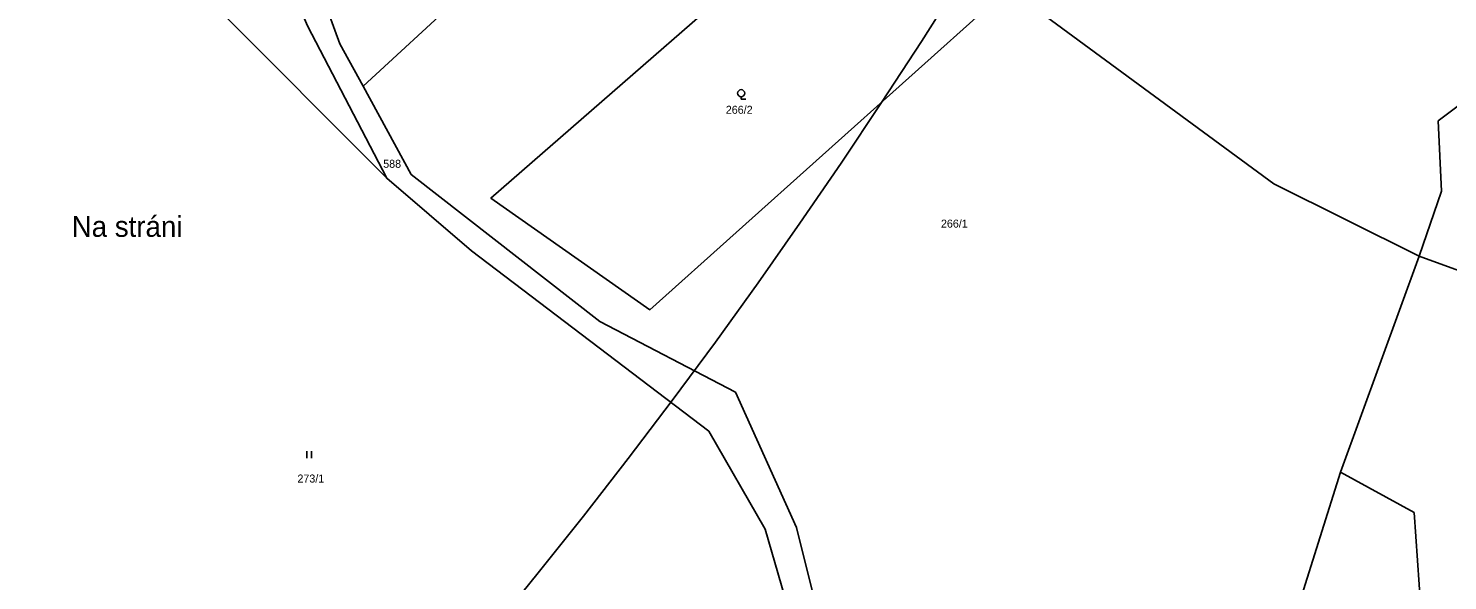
# Model space of a CAD drawing. Extents: x -680203 to -673936, y -1102717 to -1093650.
# Drawn here: x -675523.1 to -675221.6, y -1100209.9 to -1100092.5 of the extents above; entities that cross this region are included whole.
import ezdxf

# ---------------------------------------------------------------- set-up
doc = ezdxf.new("R2010")
doc.units = 0
for name, color, linetype in [('_Ideová část', 7, 'Continuous'), ('SOxx02xx_Staničení_Popis10', 7, 'Continuous'), ('SOxxxxxx_Koleje_hlavní_body_Popis10', 7, 'Continuous'), ('SOxxxxxx_Osa_bod_P', 7, 'Continuous'), ('x_prac', 7, 'Continuous')]:
    doc.layers.add(name, color=color, linetype=linetype)

msp = doc.modelspace()

# ---------------------------------------------------------------- linework, layer by layer
at = {"layer": '_Ideová část'}
msp.add_circle((-676417.7, -1099401.52), 1287.12, dxfattribs=at)
at = {"layer": 'SOxxxxxx_Koleje_hlavní_body_Popis10'}
for p, q in [((-675371.64, -1100107.03), (-675371.64, -1100107.53)), ((-675371.64, -1100107.53), (-675370.64, -1100107.53)), ((-675463.89, -1100183.86), (-675463.89, -1100182.36)), ((-675462.89, -1100183.86), (-675462.89, -1100182.36))]:
    msp.add_line(p, q, dxfattribs=at)
msp.add_circle((-675371.64, -1100106.28), 0.75, dxfattribs=at)
at = {"layer": 'x_prac'}
for p, q in [((-675414.33, -1100070.11), (-675451.95, -1100104.77)), ((-675244.33, -1100186.85), (-675227.61, -1100140.95))]:
    msp.add_line(p, q, dxfattribs=at)
for points in [[(-675488.6, -1099986.94), (-675490.8, -1100001.83), (-675490.85, -1100016.83), (-675483.97, -1100036.22), (-675479.36, -1100047.75), (-675463.07, -1100078.83), (-675456.93, -1100095.79), (-675451.95, -1100104.77)], [(-675504.01, -1100008.13), (-675497.05, -1100017.87), (-675485.06, -1100046.49), (-675472.26, -1100072.14), (-675463.76, -1100091.96), (-675446.93, -1100124.36)], [(-675227.61, -1100140.95), (-675258.46, -1100125.54), (-675331.04, -1100072.09), (-675370.73, -1100040.57), (-675378.15, -1100035.65)], [(-675446.93, -1100124.36), (-675483.47, -1100087.73), (-675482.46, -1100073.03), (-675526.45, -1100042.02), (-675541.96, -1100056.8)], [(-675317.7, -1100086.57), (-675391.04, -1100152.33), (-675424.81, -1100128.59), (-675349.68, -1100063.08), (-675317.7, -1100086.57)], [(-675227.61, -1100140.95), (-675222.85, -1100127.09), (-675223.59, -1100112.18), (-675207.93, -1100100.43)], [(-675451.95, -1100104.77), (-675441.73, -1100123.56), (-675401.64, -1100154.85), (-675372.85, -1100169.87), (-675359.9, -1100198.59), (-675347.26, -1100249.26), (-675337.16, -1100259.86), (-675318.61, -1100283.44)], [(-675344.14, -1100258.95), (-675351.41, -1100251.25), (-675366.51, -1100198.94), (-675378.54, -1100178.11), (-675428.96, -1100139.82), (-675446.93, -1100124.36)], [(-675227.61, -1100140.95), (-675204.48, -1100149.34), (-675198.43, -1100161.15), (-675198.38, -1100171.91)], [(-675244.33, -1100186.85), (-675252.98, -1100214.36), (-675263.97, -1100229.42), (-675265.63, -1100248.34), (-675275.06, -1100268.25), (-675279.29, -1100273.53)], [(-675246.15, -1100269.9), (-675236.86, -1100232.59), (-675226.94, -1100220.92), (-675228.67, -1100195.42), (-675244.33, -1100186.85)]]:
    msp.add_lwpolyline(points, dxfattribs=at)

# ---------------------------------------------------------------- texts
at = {"layer": 'SOxx02xx_Staničení_Popis10'}
msp.add_text('Na stráni', height=4.4, dxfattribs=at).set_placement((-675513.86, -1100136.82))
at = {"layer": 'SOxxxxxx_Osa_bod_P'}
for s, p in [('266/2', (-675374.9, -1100110.66)), ('588', (-675447.68, -1100122.14)), ('266/1', (-675329.2, -1100134.86)), ('273/1', (-675465.9, -1100189.05))]:
    msp.add_text(s, height=1.7, dxfattribs=at).set_placement(p)

doc.saveas('drawing.dxf')
